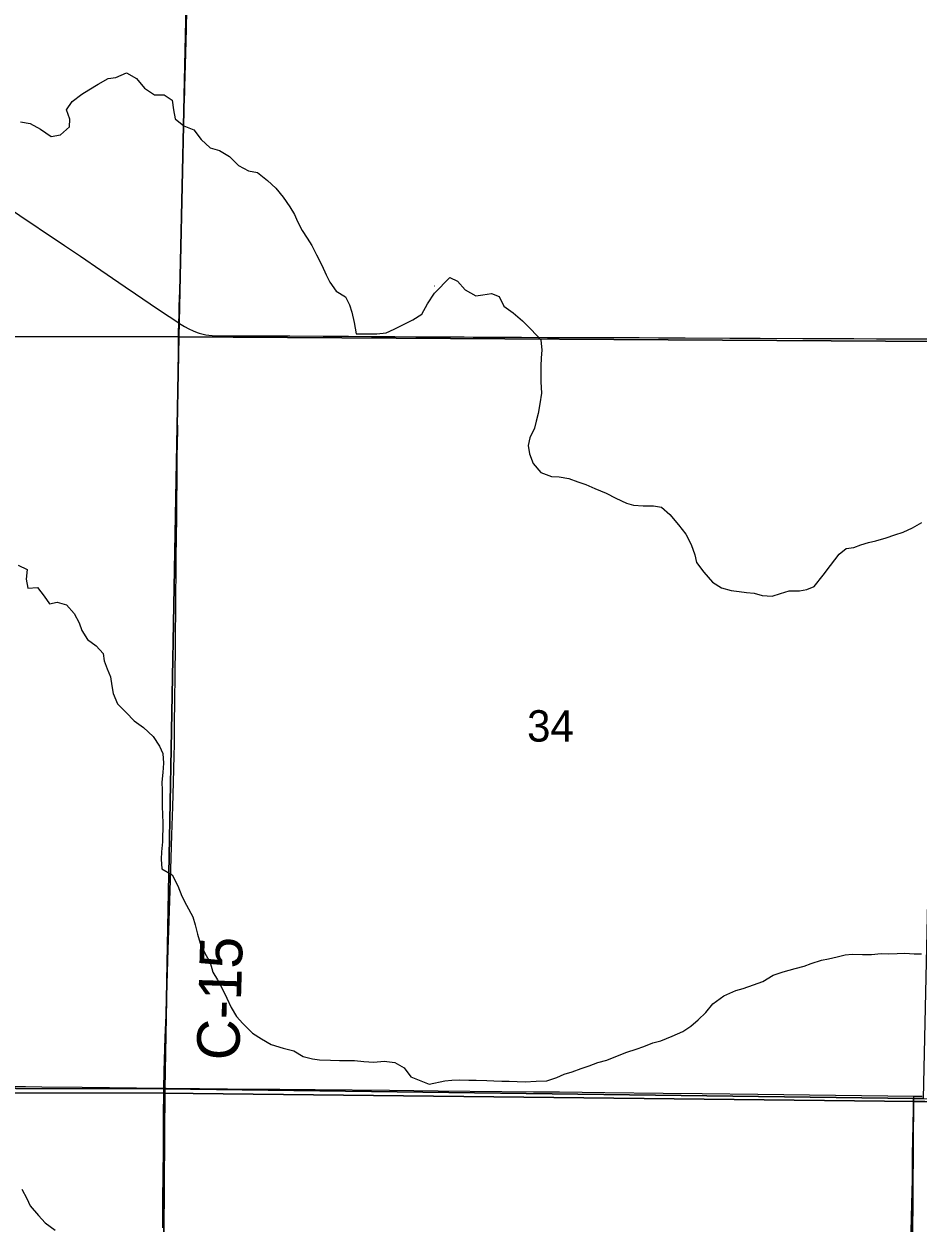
# Model space of a CAD drawing. Extents: x 0 to 34, y 0 to 22.
# Drawn here: x 6.886 to 7.481, y 17.325 to 18.124 of the extents above; entities that cross this region are included whole.
import ezdxf

# ---------------------------------------------------------------- set-up
doc = ezdxf.new("R2010")
doc.units = 0
for name, color, linetype in [('GM_X_County_Road', 7, 'Continuous'), ('GM_X_County_Road_Text', 7, 'Continuous'), ('GM_X_Minor_River', 7, 'Continuous'), ('GM_X_Section', 7, 'Continuous'), ('GM_X_Section_Text', 7, 'Continuous'), ('GM_X_Township', 7, 'Continuous'), ('GM_X_Township_Road', 7, 'Continuous'), ('GM_X_US_Route', 7, 'Continuous')]:
    doc.layers.add(name, color=color, linetype=linetype)

msp = doc.modelspace()

# ---------------------------------------------------------------- linework, layer by layer
at = {"layer": 'GM_X_County_Road'}
for points in [[(6.98873, 17.92477), (6.98891, 17.93055), (6.98899, 17.93272), (6.9891, 17.93582), (6.98956, 17.95135), (6.98985, 17.96347), (6.99009, 17.97372), (6.99029, 17.98398), (6.99072, 17.99734), (6.99106, 18.01007), (6.99122, 18.01846), (6.99127, 18.02156), (6.99135, 18.0256), (6.99139, 18.02746), (6.99152, 18.03242), (6.99173, 18.03894), (6.99183, 18.0439), (6.9919, 18.04669), (6.99214, 18.06203), (6.99232, 18.06938), (6.99274, 18.07838), (6.99284, 18.08241), (6.993, 18.08925), (6.99322, 18.0967), (6.99381, 18.12062), (6.99406, 18.13336)], [(6.87375, 18.00264), (6.8871, 17.99354), (6.89279, 17.98974), (6.89793, 17.98624), (6.90436, 17.98189), (6.91262, 17.97635), (6.92316, 17.9692), (6.93674, 17.95987), (6.94885, 17.95171), (6.95296, 17.9489), (6.95988, 17.94416), (6.96962, 17.93748), (6.97323, 17.93505), (6.98225, 17.92898), (6.98873, 17.92477)], [(6.97877, 17.4147), (6.97896, 17.42568), (6.97943, 17.44121), (6.9797, 17.44835), (6.98028, 17.46326), (6.98064, 17.47506), (6.98095, 17.48407), (6.9817, 17.50737), (6.9822, 17.51948), (6.98305, 17.54619), (6.98364, 17.56794), (6.98417, 17.58347), (6.98472, 17.60211), (6.98514, 17.61858), (6.9856, 17.63629), (6.9858, 17.64374), (6.98596, 17.65834), (6.98611, 17.67202), (6.98626, 17.69067), (6.9865, 17.70869), (6.98666, 17.72144), (6.98678, 17.72858), (6.98687, 17.73386), (6.98707, 17.76774), (6.98728, 17.78266), (6.98737, 17.79415), (6.98739, 17.80255), (6.98761, 17.82306), (6.98766, 17.82959), (6.98774, 17.83612), (6.98785, 17.84389), (6.988, 17.85383), (6.98799, 17.85973), (6.98812, 17.87403), (6.9882, 17.87962), (6.98833, 17.8877), (6.98841, 17.89609), (6.98846, 17.90137), (6.98849, 17.90479), (6.98852, 17.90758), (6.98854, 17.91038), (6.98858, 17.91379), (6.98863, 17.91814), (6.98873, 17.92465), (6.98873, 17.92477)], [(6.98873, 17.92477), (6.98924, 17.92444), (6.99264, 17.92232), (6.99534, 17.92083), (6.99841, 17.91942), (7.00089, 17.91845), (7.00232, 17.91795), (7.00418, 17.9174), (7.00686, 17.9168), (7.00883, 17.91653), (7.0109, 17.91635), (7.01583, 17.91613), (7.02515, 17.91609), (7.03448, 17.91612), (7.04846, 17.91605), (7.06275, 17.91605), (7.08489, 17.91597)], [(7.08489, 17.91597), (7.08917, 17.91596), (7.10192, 17.91589), (7.11714, 17.91576), (7.13268, 17.91562), (7.14666, 17.91557), (7.15319, 17.91555), (7.16748, 17.91556), (7.17898, 17.91544), (7.18488, 17.91531), (7.18954, 17.9153), (7.19855, 17.9153), (7.2172, 17.91516), (7.2346, 17.91501), (7.24983, 17.915), (7.27282, 17.91494), (7.28152, 17.91497), (7.29551, 17.915), (7.30857, 17.91487), (7.31665, 17.91477), (7.32628, 17.91476), (7.35611, 17.91462), (7.37632, 17.91456), (7.4046, 17.91442), (7.41889, 17.91442), (7.42978, 17.91437), (7.43879, 17.91426), (7.4537, 17.91421), (7.47422, 17.91413), (7.49131, 17.91417)]]:
    msp.add_lwpolyline(points, dxfattribs=at)
at = {"layer": 'GM_X_Minor_River'}
for points in [[(6.88319, 18.05882), (6.88963, 18.05763), (6.89663, 18.05397), (6.90361, 18.04899), (6.90988, 18.05008), (6.91599, 18.05554), (6.91603, 18.06066), (6.91398, 18.06675), (6.91763, 18.07241), (6.92412, 18.0773), (6.92888, 18.08011), (6.93498, 18.08386), (6.94165, 18.0876), (6.94678, 18.08832), (6.95382, 18.09149), (6.96062, 18.08765), (6.96589, 18.08116), (6.9725, 18.07674), (6.97895, 18.07669), (6.98442, 18.07324), (6.98514, 18.06678), (6.98642, 18.0607), (6.99208, 18.0561), (6.9987, 18.0534), (7.00358, 18.04691), (7.00962, 18.04155), (7.01586, 18.03961), (7.02248, 18.03576), (7.0285, 18.02964), (7.03531, 18.02618), (7.04118, 18.02499), (7.04797, 18.01963), (7.05344, 18.01466), (7.05833, 18.00855), (7.06283, 18.00206), (7.06583, 17.99711), (7.06789, 17.99235), (7.07107, 17.98644), (7.07426, 17.9813), (7.07745, 17.97634), (7.08063, 17.97005), (7.08399, 17.9632), (7.08698, 17.95691), (7.08941, 17.95196), (7.09373, 17.94586), (7.09997, 17.9422), (7.10258, 17.93687), (7.10407, 17.93193), (7.10572, 17.92508), (7.107, 17.91749), (7.12066, 17.91738), (7.12692, 17.91809), (7.13225, 17.92052), (7.14482, 17.92688), (7.15073, 17.93063), (7.15457, 17.93743), (7.15928, 17.94449)], [(7.15928, 17.94449), (7.16949, 17.95494), (7.17441, 17.95264), (7.1797, 17.94673), (7.18671, 17.94272), (7.19146, 17.94346), (7.19715, 17.94438), (7.20227, 17.94227), (7.20547, 17.936), (7.21152, 17.93142), (7.21795, 17.92607), (7.22363, 17.92036), (7.23005, 17.9135), (7.23078, 17.90666), (7.23019, 17.90154), (7.22998, 17.89585), (7.22995, 17.89035), (7.23012, 17.88541), (7.23047, 17.87801), (7.2293, 17.8708), (7.22833, 17.86435), (7.22698, 17.85923), (7.22582, 17.85449), (7.22275, 17.84805), (7.22159, 17.84312), (7.22252, 17.83743), (7.22496, 17.83096), (7.23006, 17.82506), (7.23726, 17.82237), (7.24238, 17.82216), (7.24864, 17.821), (7.25471, 17.81888), (7.26001, 17.81715), (7.26607, 17.81447), (7.27365, 17.81121), (7.28009, 17.80796), (7.2871, 17.8047), (7.29184, 17.80335), (7.29829, 17.80276), (7.30513, 17.80292), (7.31043, 17.80195), (7.31611, 17.79699), (7.32177, 17.79013), (7.32668, 17.78385), (7.33026, 17.777), (7.3327, 17.77016), (7.33381, 17.76503), (7.33872, 17.75856), (7.34458, 17.75189), (7.35045, 17.74826), (7.35689, 17.74634), (7.3622, 17.74574), (7.36713, 17.74496), (7.37226, 17.74456), (7.37756, 17.74302), (7.38421, 17.74262), (7.38991, 17.7443), (7.39561, 17.74617), (7.40244, 17.74614), (7.40738, 17.74707), (7.41232, 17.74895), (7.41824, 17.75671), (7.4232, 17.76314), (7.42892, 17.7707), (7.43368, 17.77429), (7.43862, 17.77503), (7.44337, 17.77672), (7.44851, 17.7784), (7.45344, 17.77952), (7.46029, 17.78139), (7.46599, 17.78345), (7.4715, 17.78533), (7.47777, 17.78815), (7.48405, 17.79173)], [(7.15907, 17.94955), (7.15908, 17.94956)], [(6.88161, 17.76321), (6.88766, 17.76032), (6.88704, 17.75388), (6.88814, 17.74799), (6.89459, 17.74832), (6.8991, 17.74259), (6.90267, 17.73744), (6.90761, 17.73854), (6.91386, 17.73679), (6.91894, 17.73106), (6.92231, 17.72477), (6.92417, 17.71982), (6.92792, 17.71372), (6.93377, 17.70951), (6.93829, 17.70435), (6.93901, 17.6996), (6.94106, 17.69408), (6.9433, 17.68894), (6.9442, 17.68286), (6.94493, 17.67774), (6.94791, 17.67088), (6.95356, 17.66515), (6.95902, 17.6596), (6.96525, 17.655), (6.97166, 17.64907), (6.97579, 17.64259), (6.97803, 17.63764), (6.97855, 17.63138), (6.97813, 17.62512), (6.97751, 17.61867), (6.97766, 17.61336), (6.97762, 17.60843), (6.97777, 17.60216), (6.97792, 17.59723), (6.97807, 17.59097), (6.97798, 17.57882), (6.97717, 17.57219), (6.97694, 17.56726), (6.97746, 17.5608), (6.98427, 17.55677), (6.98801, 17.54953), (6.9908, 17.54268), (6.99398, 17.53658), (6.9981, 17.52877), (6.99977, 17.52364), (7.00125, 17.51737), (7.0031, 17.51128), (7.00608, 17.50462), (7.00964, 17.49833), (7.0115, 17.49206), (7.01449, 17.48691), (7.01711, 17.48196), (7.02066, 17.47472), (7.02365, 17.46844), (7.02722, 17.46253), (7.03136, 17.45776), (7.03795, 17.45125), (7.0438, 17.44761), (7.05042, 17.44376), (7.05837, 17.44124), (7.06537, 17.43947), (7.07161, 17.43582), (7.07786, 17.43426)], [(7.15565, 17.41732), (7.1661, 17.41959), (7.17085, 17.41995), (7.17598, 17.42012), (7.18205, 17.4201), (7.18698, 17.41988), (7.194, 17.41986), (7.19875, 17.41965), (7.20406, 17.41943), (7.20899, 17.41922), (7.21431, 17.41901), (7.21962, 17.41899), (7.22684, 17.41934), (7.23405, 17.4195), (7.2407, 17.42175), (7.24564, 17.424), (7.25097, 17.4255), (7.25686, 17.42775), (7.26237, 17.42962), (7.26807, 17.43169), (7.27415, 17.43337), (7.28119, 17.43619), (7.28746, 17.43863), (7.29354, 17.44069), (7.29868, 17.44238), (7.30476, 17.44482), (7.31008, 17.44631), (7.31768, 17.44932), (7.32472, 17.45232), (7.33005, 17.45591), (7.335, 17.46025), (7.33996, 17.46516), (7.34472, 17.47084), (7.35196, 17.47612), (7.35995, 17.47969), (7.36489, 17.481), (7.37192, 17.48344), (7.378, 17.48569), (7.38485, 17.49002), (7.39169, 17.49227), (7.39948, 17.49433), (7.40557, 17.49601), (7.41032, 17.4977), (7.41716, 17.49995), (7.42191, 17.50087), (7.42761, 17.50218), (7.43293, 17.50348), (7.43767, 17.50403), (7.4445, 17.50381), (7.45039, 17.50379), (7.45684, 17.50433), (7.46159, 17.50412), (7.46766, 17.50448), (7.4726, 17.50465), (7.47886, 17.50424), (7.48379, 17.50422)], [(7.07786, 17.43426), (7.0826, 17.43365), (7.0898, 17.43341), (7.09587, 17.43317), (7.10119, 17.43313), (7.10593, 17.4331), (7.112, 17.43248), (7.11882, 17.43205), (7.12566, 17.43257), (7.13267, 17.43176), (7.13891, 17.42811), (7.14342, 17.42219), (7.15565, 17.41732)], [(6.88407, 17.34731), (6.88744, 17.34121), (6.88968, 17.33626), (6.89514, 17.32977), (6.89965, 17.3248), (6.90626, 17.32001)]]:
    msp.add_lwpolyline(points, dxfattribs=at)
at = {"layer": 'GM_X_Section'}
for points in [[(6.99984, 18.41775), (6.98884, 17.91553), (6.4928, 17.91626), (6.50305, 18.41943)], [(6.99984, 18.41775), (7.50153, 18.41698), (7.49596, 17.91244), (6.98884, 17.91553)], [(6.98884, 17.91553), (6.97935, 17.41426), (6.48295, 17.41537), (6.4928, 17.91626)], [(6.98884, 17.91553), (7.49596, 17.91244), (7.4849, 17.40776), (7.47845, 17.4078), (6.97935, 17.41426)], [(6.47745, 17.41541), (6.48295, 17.41537), (6.97935, 17.41426), (6.97584, 16.9012), (6.47069, 16.89897)], [(6.97935, 17.41426), (7.47845, 17.4078), (7.47479, 16.90534), (6.97584, 16.9012)], [(7.47845, 17.4078), (7.4849, 17.40776), (7.97601, 17.40757), (7.9678, 16.90665), (7.47479, 16.90534)]]:
    msp.add_lwpolyline(points, close=True, dxfattribs=at)
at = {"layer": 'GM_X_Township'}
for points in [[(6.78218, 20.41492), (7.02348, 20.4144), (7.09974, 20.41612), (7.18499, 20.41333), (7.20165, 20.41351), (7.32949, 20.41334), (7.74573, 20.4181), (7.8262, 20.42148), (7.97527, 20.42654), (8.50107, 20.45272), (8.493, 20.16746), (8.48607, 19.91593), (8.486, 19.91208), (8.49318, 19.41213), (8.49927, 18.91004), (8.49985, 18.40187), (8.49713, 17.90434), (8.4927, 17.4064), (7.9915, 17.4046), (7.97617, 17.40455), (7.48595, 17.40578), (7.4791, 17.40579), (6.97838, 17.41123), (6.85112, 17.41144)], [(5.45812, 16.85635), (5.46352, 17.41199), (5.85482, 17.41232), (6.21985, 17.41235), (6.41604, 17.41268), (6.74587, 17.41079), (6.85112, 17.41144), (6.97838, 17.41123), (7.4791, 17.40579), (7.48595, 17.40578), (7.97617, 17.40455), (7.9915, 17.4046), (8.4927, 17.4064), (8.48897, 16.91291)]]:
    msp.add_lwpolyline(points, dxfattribs=at)
at = {"layer": 'GM_X_Township_Road'}
for points in [[(6.97814, 17.32159), (6.97814, 17.32687), (6.97816, 17.34147), (6.97829, 17.35546), (6.97846, 17.37504), (6.97855, 17.39525), (6.97874, 17.41278), (6.97877, 17.4147)], [(7.47675, 17.30814), (7.47719, 17.32897), (7.47755, 17.34574), (7.4777, 17.35382), (7.4778, 17.37027), (7.47838, 17.40042), (7.47856, 17.40728), (7.47861, 17.40939)]]:
    msp.add_lwpolyline(points, dxfattribs=at)
at = {"layer": 'GM_X_US_Route'}
for points in [[(6.79101, 17.41442), (6.79288, 17.4144), (6.80934, 17.41457), (6.83077, 17.41513), (6.84817, 17.41559), (6.85011, 17.41562), (6.86433, 17.41583), (6.88236, 17.41575), (6.88666, 17.41571)], [(6.88666, 17.41571), (6.89757, 17.41562), (6.92431, 17.41539), (6.97877, 17.4147), (6.98025, 17.41468), (7.00262, 17.4144), (7.02126, 17.41428), (7.05607, 17.41393), (7.07969, 17.4137), (7.1291, 17.41327), (7.16173, 17.41297), (7.204, 17.41251), (7.22514, 17.41226), (7.24254, 17.41213), (7.27269, 17.41177), (7.31154, 17.41135), (7.33764, 17.41103), (7.37462, 17.41055), (7.42653, 17.40989), (7.47861, 17.40939), (7.48432, 17.40933)]]:
    msp.add_lwpolyline(points, dxfattribs=at)

# ---------------------------------------------------------------- texts
at = {"layer": 'GM_X_County_Road_Text'}
msp.add_text('C-15', height=0.028409, rotation=88.30675, dxfattribs=at).set_placement((7.029, 17.4329))
at = {"layer": 'GM_X_Section_Text'}
msp.add_text('34', height=0.020928, rotation=0.00001, dxfattribs=at).set_placement((7.22091, 17.64566))

doc.saveas('drawing.dxf')
